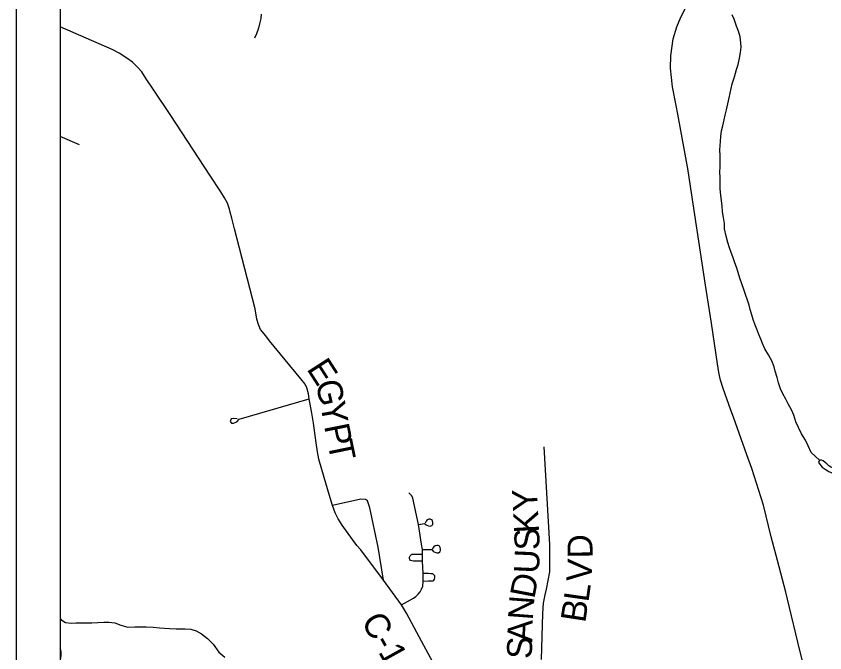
# Model space of a CAD drawing. Extents: x 0 to 34, y 0 to 22.
# Drawn here: x 2 to 3.839, y 17.231 to 18.679 of the extents above; entities that cross this region are included whole.
import ezdxf

# ---------------------------------------------------------------- set-up
doc = ezdxf.new("R2010")
doc.units = 0
for name, color, linetype in [('GM_X_Corporation', 7, 'Continuous'), ('GM_X_County_Road', 7, 'Continuous'), ('GM_X_County_Road_Text', 7, 'Continuous'), ('GM_X_Major_River', 7, 'Continuous'), ('GM_X_Minor_River', 7, 'Continuous'), ('GM_X_State_Route', 7, 'Continuous'), ('GM_X_Township_Road', 7, 'Continuous'), ('SH_Data', 7, 'Continuous')]:
    doc.layers.add(name, color=color, linetype=linetype)

msp = doc.modelspace()

# ---------------------------------------------------------------- linework, layer by layer
at = {"layer": 'GM_X_Corporation'}
msp.add_line((2.1, 20.9), (2.1, 15.8164), dxfattribs=at)
msp.add_lwpolyline([(4.892, 20.9), (2.1, 20.9), (2.1, 15.9991)], dxfattribs=at)
at = {"layer": 'GM_X_County_Road'}
msp.add_line((2.1441, 18.3862), (2.1, 18.4054), dxfattribs=at)
for points in [[(2.487, 18.2329), (2.4853, 18.2396), (2.4804, 18.2535), (2.474, 18.2655), (2.4657, 18.279), (2.4406, 18.317), (2.3519, 18.4526), (2.3117, 18.513), (2.2959, 18.5367), (2.2858, 18.5525), (2.2768, 18.5619), (2.2644, 18.5739), (2.252, 18.5833), (2.2343, 18.5945), (2.2182, 18.6028), (2.1, 18.6545)], [(2.9533, 17.1998), (2.9112, 17.2768), (2.8876, 17.3208), (2.8767, 17.34), (2.8357, 17.3963), (2.7835, 17.4647), (2.7745, 17.4752), (2.7411, 17.5214), (2.7324, 17.5353), (2.7257, 17.5488), (2.7197, 17.5661), (2.7118, 17.5909), (2.7001, 17.6296), (2.6885, 17.6716), (2.6855, 17.6878), (2.6825, 17.7084), (2.6761, 17.7528), (2.6727, 17.7757), (2.6663, 17.8087), (2.6648, 17.8196), (2.6611, 17.8332), (2.6573, 17.8422), (2.6475, 17.8538), (2.5765, 17.9406), (2.5679, 17.9518), (2.5559, 17.9661), (2.551, 17.9774), (2.5476, 17.9894), (2.5439, 18.0131), (2.5138, 18.1276), (2.4965, 18.1953), (2.4905, 18.2197), (2.487, 18.2329)], [(3.1948, 17.2155), (3.1976, 17.3201), (3.1996, 17.3435), (3.2031, 17.3624), (3.2061, 17.3759), (3.2135, 17.4153), (3.2135, 17.4768), (3.2006, 17.6992)]]:
    msp.add_lwpolyline(points, dxfattribs=at)
at = {"layer": 'GM_X_Major_River'}
msp.add_lwpolyline([(3.8596, 17.6506), (3.8526, 17.6528), (3.8481, 17.6559), (3.844, 17.6604), (3.8402, 17.6639), (3.8357, 17.6673), (3.8312, 17.6693), (3.827, 17.6689), (3.8251, 17.664), (3.8333, 17.653), (3.8401, 17.6483), (3.848, 17.6433), (3.8533, 17.641), (3.8624, 17.6371)], dxfattribs=at)
at = {"layer": 'GM_X_Minor_River'}
for points in [[(2.5569, 18.6831), (2.5564, 18.6733), (2.5537, 18.6612), (2.5509, 18.6513), (2.5463, 18.6389), (2.542, 18.6287)], [(3.827, 17.6689), (3.8082, 17.6866), (3.8015, 17.7018), (3.7948, 17.7148), (3.7858, 17.7285), (3.7791, 17.743), (3.7735, 17.7563), (3.7684, 17.7711), (3.7632, 17.7833), (3.7557, 17.797), (3.7501, 17.8077), (3.7434, 17.8195), (3.7386, 17.831), (3.7337, 17.8447), (3.7308, 17.8568), (3.7264, 17.8713), (3.7238, 17.8812), (3.7183, 17.8949), (3.7112, 17.9082), (3.7029, 17.9223), (3.6977, 17.9345), (3.6937, 17.944), (3.6888, 17.9551), (3.6844, 17.9669), (3.6803, 17.9783), (3.6762, 17.9893), (3.6725, 18.0019), (3.6696, 18.0114), (3.6667, 18.0217), (3.663, 18.0327), (3.6596, 18.0437), (3.6552, 18.057), (3.6504, 18.0704), (3.646, 18.0829), (3.6423, 18.0955), (3.6382, 18.108), (3.6345, 18.1179), (3.6297, 18.1316), (3.626, 18.1411), (3.6223, 18.1518), (3.6186, 18.164), (3.6149, 18.1784), (3.6113, 18.1948), (3.6106, 18.2073), (3.6085, 18.221), (3.6067, 18.2339), (3.6057, 18.2475), (3.6042, 18.2585), (3.6028, 18.2718), (3.6014, 18.2863), (3.6008, 18.3007), (3.6009, 18.3121), (3.6006, 18.3246), (3.6011, 18.3356), (3.6012, 18.3473), (3.601, 18.3621), (3.6007, 18.3746), (3.6011, 18.3841), (3.602, 18.3944), (3.6028, 18.405), (3.6045, 18.4182), (3.6068, 18.4292), (3.61, 18.4432), (3.6127, 18.4534), (3.6155, 18.4655), (3.6186, 18.4795), (3.6214, 18.4932), (3.6238, 18.5034), (3.6258, 18.5144), (3.6285, 18.525), (3.6336, 18.5412), (3.6386, 18.5579), (3.6418, 18.5688), (3.6449, 18.5832), (3.6473, 18.5961), (3.6485, 18.6086), (3.6479, 18.6181), (3.6465, 18.6318), (3.6428, 18.6451), (3.638, 18.6565), (3.6328, 18.6717), (3.6283, 18.682)], [(2.1, 17.3089), (2.1017, 17.3067), (2.1123, 17.2997)], [(2.1123, 17.2997), (2.1251, 17.2985), (2.1354, 17.2991), (2.1596, 17.2989), (2.1721, 17.2992), (2.1858, 17.2994), (2.1994, 17.3001), (2.2104, 17.3003), (2.2241, 17.2987), (2.2384, 17.2936), (2.2543, 17.2893), (2.2702, 17.2896), (2.2854, 17.2898), (2.2956, 17.2897), (2.3115, 17.2888), (2.3263, 17.2875), (2.3377, 17.2867), (2.349, 17.2862), (2.3642, 17.2853), (2.3843, 17.2851), (2.3971, 17.2846), (2.4092, 17.2811), (2.4217, 17.2741), (2.4352, 17.263), (2.4484, 17.2504)], [(2.4484, 17.2504), (2.4612, 17.232), (2.4747, 17.2205)]]:
    msp.add_lwpolyline(points, dxfattribs=at)
at = {"layer": 'GM_X_State_Route'}
msp.add_line((3.662, 17.6812), (3.6315, 17.7667), dxfattribs=at)
for points in [[(3.5007, 18.476), (3.4926, 18.5178), (3.4879, 18.5603), (3.4886, 18.5886), (3.494, 18.627), (3.5027, 18.6546), (3.5115, 18.6769), (3.5236, 18.6998), (3.5385, 18.7247), (3.5654, 18.7584), (3.6079, 18.8049), (3.6434, 18.8475)], [(3.5281, 18.3281), (3.5045, 18.456), (3.5007, 18.476)], [(3.6315, 17.7667), (3.6257, 17.7828), (3.6079, 17.8322), (3.602, 17.8509), (3.5977, 17.8682), (3.5949, 17.8878), (3.5812, 17.9807), (3.5675, 18.067), (3.5283, 18.3271), (3.5281, 18.3281)], [(3.7313, 17.4405), (3.7171, 17.4948), (3.6993, 17.5668), (3.6732, 17.6499), (3.662, 17.6812)], [(3.754, 17.353), (3.7501, 17.3687), (3.7313, 17.4405)], [(3.807, 17.1378), (3.7825, 17.2362), (3.754, 17.353)]]:
    msp.add_lwpolyline(points, dxfattribs=at)
at = {"layer": 'GM_X_Township_Road'}
msp.add_line((2.9239, 17.4658), (2.9428, 17.4656), dxfattribs=at)
for points in [[(2.5025, 17.7629), (2.4946, 17.7637), (2.4886, 17.7629), (2.4868, 17.7569), (2.4898, 17.7528), (2.4946, 17.7528), (2.5018, 17.7558), (2.5074, 17.7622), (2.6663, 17.8087)], [(2.8767, 17.34), (2.9033, 17.3554), (2.9088, 17.3592), (2.9143, 17.3644), (2.9185, 17.3694), (2.922, 17.3756), (2.9245, 17.3827), (2.926, 17.3939), (2.9257, 17.4109), (2.9243, 17.4396), (2.924, 17.455), (2.9239, 17.4658), (2.9217, 17.4779), (2.9147, 17.5228), (2.9021, 17.5823), (2.8998, 17.5876), (2.8928, 17.5949)], [(2.8357, 17.3963), (2.8233, 17.4714), (2.804, 17.5607), (2.7993, 17.5761), (2.7942, 17.5797), (2.7839, 17.5805), (2.7197, 17.5661)], [(2.9327, 17.5219), (2.9343, 17.5208), (2.9378, 17.5194), (2.9414, 17.519), (2.9451, 17.5203), (2.9474, 17.523), (2.9479, 17.5266), (2.9469, 17.5315), (2.9449, 17.5333), (2.9418, 17.5345), (2.9387, 17.5345), (2.9367, 17.5342), (2.935, 17.5331), (2.9328, 17.5301), (2.9303, 17.5259)], [(2.9147, 17.5228), (2.9287, 17.5246), (2.9327, 17.5219)], [(2.9428, 17.4656), (2.9457, 17.4656), (2.9487, 17.4621), (2.9507, 17.4607), (2.9543, 17.4589), (2.9573, 17.4584), (2.9606, 17.4585), (2.9633, 17.4607), (2.9647, 17.4634), (2.9651, 17.4662), (2.9646, 17.47), (2.9625, 17.4733), (2.9599, 17.4747), (2.9565, 17.4748), (2.9533, 17.474), (2.9499, 17.4718), (2.9461, 17.4671)], [(2.9243, 17.4396), (2.9082, 17.4391), (2.9034, 17.4392), (2.8997, 17.4397), (2.8969, 17.441), (2.8954, 17.4427), (2.8945, 17.4452), (2.8946, 17.4486), (2.8958, 17.4511), (2.8979, 17.4532), (2.9002, 17.4548), (2.9067, 17.4553), (2.924, 17.455)], [(2.926, 17.3939), (2.9377, 17.3942), (2.9451, 17.3942), (2.9479, 17.3948), (2.9501, 17.3959), (2.9516, 17.3986), (2.9519, 17.4016), (2.9518, 17.406), (2.9507, 17.4075), (2.9493, 17.4088), (2.9475, 17.4102), (2.9428, 17.4107), (2.9378, 17.4109), (2.9257, 17.4109)], [(2.1012, 17.2177), (2.1021, 17.2254), (2.1024, 17.2325), (2.1017, 17.2379), (2.1, 17.2402)]]:
    msp.add_lwpolyline(points, dxfattribs=at)
at = {"layer": 'SH_Data'}
for p, q in [((2, 21), (2, 14)), ((2.1, 20.9), (2.1, 14.1))]:
    msp.add_line(p, q, dxfattribs=at)

# ---------------------------------------------------------------- texts
at = {"layer": 'GM_X_County_Road_Text'}
for s, height, rotation, p in [('E', 0.0568, 302.7272, (2.6594, 17.8766)), ('G', 0.0568, 282.8532, (2.6804, 17.8456)), ('Y', 0.0568, 279.8288, (2.6913, 17.7977)), ('P', 0.0568, 281.4048, (2.7002, 17.7467)), ('T', 0.0568, 281.707, (2.7078, 17.7088)), ('Y', 0.0568, 93.0656, (3.1869, 17.5544)), ('K', 0.0568, 93.0072, (3.1895, 17.5044)), ('S', 0.0568, 92.2173, (3.191, 17.4652)), ('D', 0.0568, 90.9042, (3.3112, 17.446)), ('U', 0.0568, 87.4911, (3.1888, 17.4101)), ('V', 0.0568, 86.1546, (3.3077, 17.391)), ('D', 0.0568, 79.1673, (3.1784, 17.3521)), ('L', 0.0568, 81.9927, (3.3013, 17.3445)), ('N', 0.0568, 85.7376, (3.1749, 17.3039)), ('B', 0.0568, 81.2544, (3.2941, 17.2976)), ('C-127', 0.05682, 299.03, (2.7836, 17.3032)), ('A', 0.0568, 88.5537, (3.1736, 17.2547)), ('S', 0.0568, 88.6267, (3.1727, 17.2164))]:
    msp.add_text(s, height=height, rotation=rotation, dxfattribs=at).set_placement(p)

doc.saveas('drawing.dxf')
